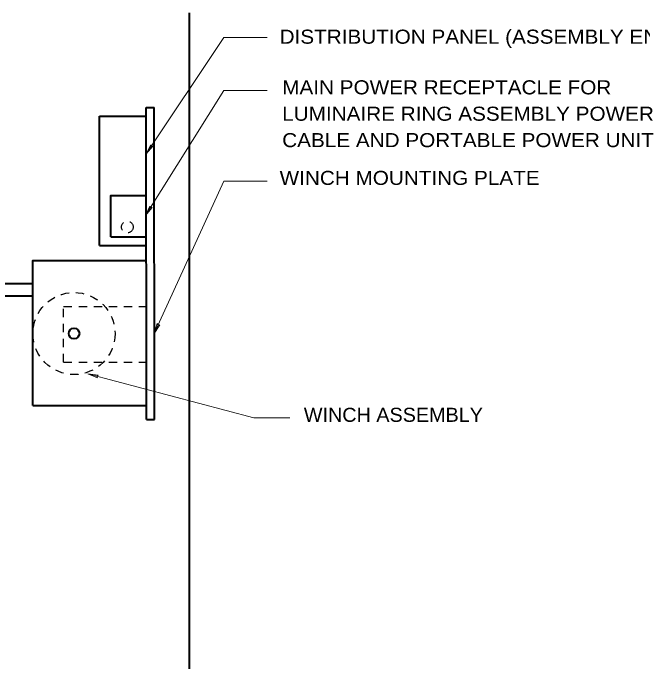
# Model space of a CAD drawing. Extents: x 312583 to 312854, y 144419 to 144597.
# Drawn here: x 312765.92 to 312799.88, y 144447.26 to 144482.26 of the extents above; entities that cross this region are included whole.
import ezdxf

# ---------------------------------------------------------------- set-up
doc = ezdxf.new("R2010")
doc.units = 0
doc.header["$LTSCALE"] = 0.3
doc.linetypes.add('SHORT_DASHED', pattern=[2.7, 1.5, -1.2])
doc.layers.add('1', color=7, linetype='Continuous', lineweight=13)
doc.layers.add('2', color=7, linetype='Continuous', lineweight=13)

msp = doc.modelspace()

# ---------------------------------------------------------------- linework, layer by layer
at = {"layer": '1', "lineweight": 40}
for p, q in [((312775.46, 144445.6231), (312775.46, 144482.2621)), ((312773.1294, 144460.3124), (312773.1217, 144477.1638)), ((312773.1217, 144477.1638), (312773.551, 144477.1638)), ((312773.5587, 144460.3124), (312773.551, 144477.1638)), ((312770.5917, 144476.6884), (312773.1217, 144476.6884)), ((312770.5917, 144469.7118), (312770.5917, 144476.6884)), ((312771.1974, 144470.1794), (312773.091, 144470.1794)), ((312770.5917, 144469.7118), (312773.1217, 144469.7118)), ((312767.0037, 144467.6264), (312762.603, 144467.6264)), ((312767.0037, 144461.0638), (312773.1294, 144461.0638)), ((312773.1294, 144460.3124), (312773.5587, 144460.3124))]:
    msp.add_line(p, q, dxfattribs=at)
at = {"layer": '1'}
for p, q in [((312777.3, 144480.9434), (312773.114, 144474.6491)), ((312773.0757, 144471.3294), (312777.3, 144478.0684)), ((312773.551, 144464.9508), (312777.3, 144473.1771))]:
    msp.add_line(p, q, dxfattribs=at)
at = {"layer": '1', "linetype": 'SHORT_DASHED', "lineweight": 25}
msp.add_line((312768.6597, 144463.4098), (312773.1294, 144463.4098), dxfattribs=at)
at = {"layer": '1'}
for points in [[(312773.4744, 144475.0708), (312773.114, 144474.6491), (312773.3594, 144475.1474), (312773.39, 144475.0631)], [(312773.4284, 144471.7588), (312773.0757, 144471.3294), (312773.3057, 144471.8354), (312773.344, 144471.7511)], [(312773.4284, 144471.7588), (312773.0757, 144471.3294), (312773.3057, 144471.8354), (312773.344, 144471.7511)], [(312773.8424, 144465.4261), (312773.551, 144464.9508), (312773.712, 144465.4874), (312773.758, 144465.4031)], [(312770.4844, 144462.5588), (312769.9707, 144462.7658), (312770.5227, 144462.6968), (312770.4537, 144462.6354)]]:
    msp.add_lwpolyline(points, close=True, dxfattribs=at)
at = {"layer": '1', "lineweight": 40}
for points in [[(312771.1974, 144470.1794), (312771.1974, 144472.4028), (312773.0757, 144472.4028)], [(312767.0037, 144461.0638), (312767.0037, 144468.8838), (312773.1294, 144468.8838)], [(312767.0037, 144466.9594), (312762.603, 144466.9594), (312762.603, 144467.6264)]]:
    msp.add_lwpolyline(points, dxfattribs=at)
at = {"layer": '1', "linetype": 'SHORT_DASHED', "lineweight": 25}
msp.add_lwpolyline([(312768.6597, 144463.4098), (312768.6597, 144466.3998), (312773.1294, 144466.3998)], dxfattribs=at)
at = {"layer": '1'}
msp.add_lwpolyline([(312769.9707, 144462.7658), (312778.9177, 144460.3891), (312780.8727, 144460.3891)], dxfattribs=at)
at = {"layer": '1', "linetype": 'SHORT_DASHED', "lineweight": 25}
for centre, radius in [((312772.0982, 144470.6989), 0.3146), ((312769.2174, 144464.9489), 2.2159)]:
    msp.add_circle(centre, radius, dxfattribs=at)
at = {"layer": '1', "lineweight": 40}
msp.add_circle((312769.2194, 144464.9508), 0.2879, dxfattribs=at)
at = {"layer": '2'}
for p, q in [((312777.3, 144480.9434), (312779.6384, 144480.9434)), ((312777.3, 144478.0684), (312779.6384, 144478.0684)), ((312777.3, 144473.1771), (312779.6384, 144473.1771))]:
    msp.add_line(p, q, dxfattribs=at)

# ---------------------------------------------------------------- texts
at = {"layer": '1'}
for s, width, p in [('DISTRIBUTION PANEL (ASSEMBLY ENCLOSED)', 1.1, (312780.3164, 144480.6006)), ('MAIN POWER RECEPTACLE FOR', 1.1, (312780.4566, 144477.8659)), ('LUMINAIRE RING ASSEMBLY POWER', 1.1, (312780.4566, 144476.4399)), ('CABLE AND PORTABLE POWER UNIT', 1.1, (312780.4566, 144475.0139)), ('WINCH MOUNTING PLATE', 1.1, (312780.3165, 144472.9746)), ('WINCH ASSEMBLY', 1.05, (312781.626, 144460.1789))]:
    msp.add_text(s, height=0.76, dxfattribs=dict(at, width=width)).set_placement(p)

doc.saveas('drawing.dxf')
